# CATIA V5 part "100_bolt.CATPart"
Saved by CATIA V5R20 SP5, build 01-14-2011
Part number: 100_bolt
Bounding box of the stored display mesh (mm): x -10.992 to 10.992, y 129.378 to 151.346, z -180.5 to -159.5
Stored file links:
  C:\Documents and Settings\anizard\Bureau\13\100_bolt.CATPart
  C:\Documents and Settings\anizard\Bureau\13\anizard.CATProduct
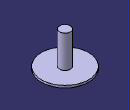
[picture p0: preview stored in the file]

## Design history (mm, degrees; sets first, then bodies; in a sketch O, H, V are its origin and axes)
Set1
  Plane1: linked copy from another document
  Line1: linked copy from another document
  Plane2: linked copy from another document
Body1 (main body)
  Sketch1 on Plane1, origin (0, 0, 0), H (0, 1, 0), V (0, 0, 1)
    line L1 (140.3619, -159.5) -> (142.8619, -159.5)
    line L2 (142.8619, -159.5) -> (142.8619, -174.5)
    line L3 (142.8619, -174.5) -> (151.3619, -174.5)
    line L4 (151.3619, -174.5) -> (151.3619, -175.5)
    line L5 (151.3619, -175.5) -> (144.6119, -175.5)
    line L6 (144.6119, -175.5) -> (144.6119, -180.5)
    line L7 (144.6119, -180.5) -> (140.3619, -180.5)
    line L8 (140.3619, -180.5) -> (140.3619, -159.5)
    reference projected line E1 (140.3619, -199.5) -> (140.3619, -79.5) from Line1
    reference intersected line E2 through (0, -174.5) direction (-1, 0) from Plane2
    distance L3 L5 = 1
    distance L8 L4 = 11
    distance L8 L2 = 2.5
    length L6 = 5
    length L7 = 4.25
    distance L1 L3 = 15
    horizontal: L1 H, L3 H, L5 H, L7 H
    vertical: L4 V, L6 V, L8 V, L2 V
    coincidence: L8 E1, L3 E2
  Shaft1: profile Sketch1, axis Line1, angle 360
  Sketch2 on face of Shaft1 from Sketch1.L7, origin (0, 0, -180.5), H (1, 0, 0), V (0, -1, 0)
    point P1 (0, -140.3619)
    point P2 (1.1547, -142.3619)
    point P3 (2.3094, -140.3619)
    point P4 (1.1547, -138.3619)
    point P5 (-1.1547, -138.3619)
    point P6 (-2.3094, -140.3619)
    point P7 (-1.1547, -142.3619)
    point P8 (1.732, -141.3619)
    line L1 (1.1547, -142.3619) -> (2.3094, -140.3619)
    line L2 (2.3094, -140.3619) -> (1.1547, -138.3619)
    line L3 (1.1547, -138.3619) -> (-1.1547, -138.3619)
    line L4 (-1.1547, -138.3619) -> (-2.3094, -140.3619)
    line L5 (-2.3094, -140.3619) -> (-1.1547, -142.3619)
    line L6 (-1.1547, -142.3619) -> (1.1547, -142.3619)
    construction line L7 (0, -140.3619) -> (1.732, -141.3619)
    construction circle A1 centre (0, -140.3619) radius 2.3094
    construction arc A2 centre (-2.3094, -140.3619) radius 2.3094 from (-1.1547, -138.3619) to (-1.1547, -142.3619) cw
    construction arc A3 centre (2.3094, -140.3619) radius 2.3094 from (1.1547, -138.3619) to (1.1547, -142.3619) ccw
    reference projected circle E1 centre (0, -140.3619) radius 4.25 from edge [face of Shaft1 from Sketch1.L7 | face of Shaft1 from Sketch1.L6]
    distance L5 L2 = 4
    coincidence: A1 P2, A1 P3, A1 P4, A1 P5, A1 P6, A1 P7, A2 P1, A3 P1
    midpoint: P8 L1
    parallelism: L1 L4
    concentricity: E1 A1
    horizontal: L3 H
  Pocket1: profile Sketch2, direction (0, 0, 1), length 4
  Fillet1: radius 0.5, on edge [face of Shaft1 from Sketch1.L7 | face of Shaft1 from Sketch1.L6]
